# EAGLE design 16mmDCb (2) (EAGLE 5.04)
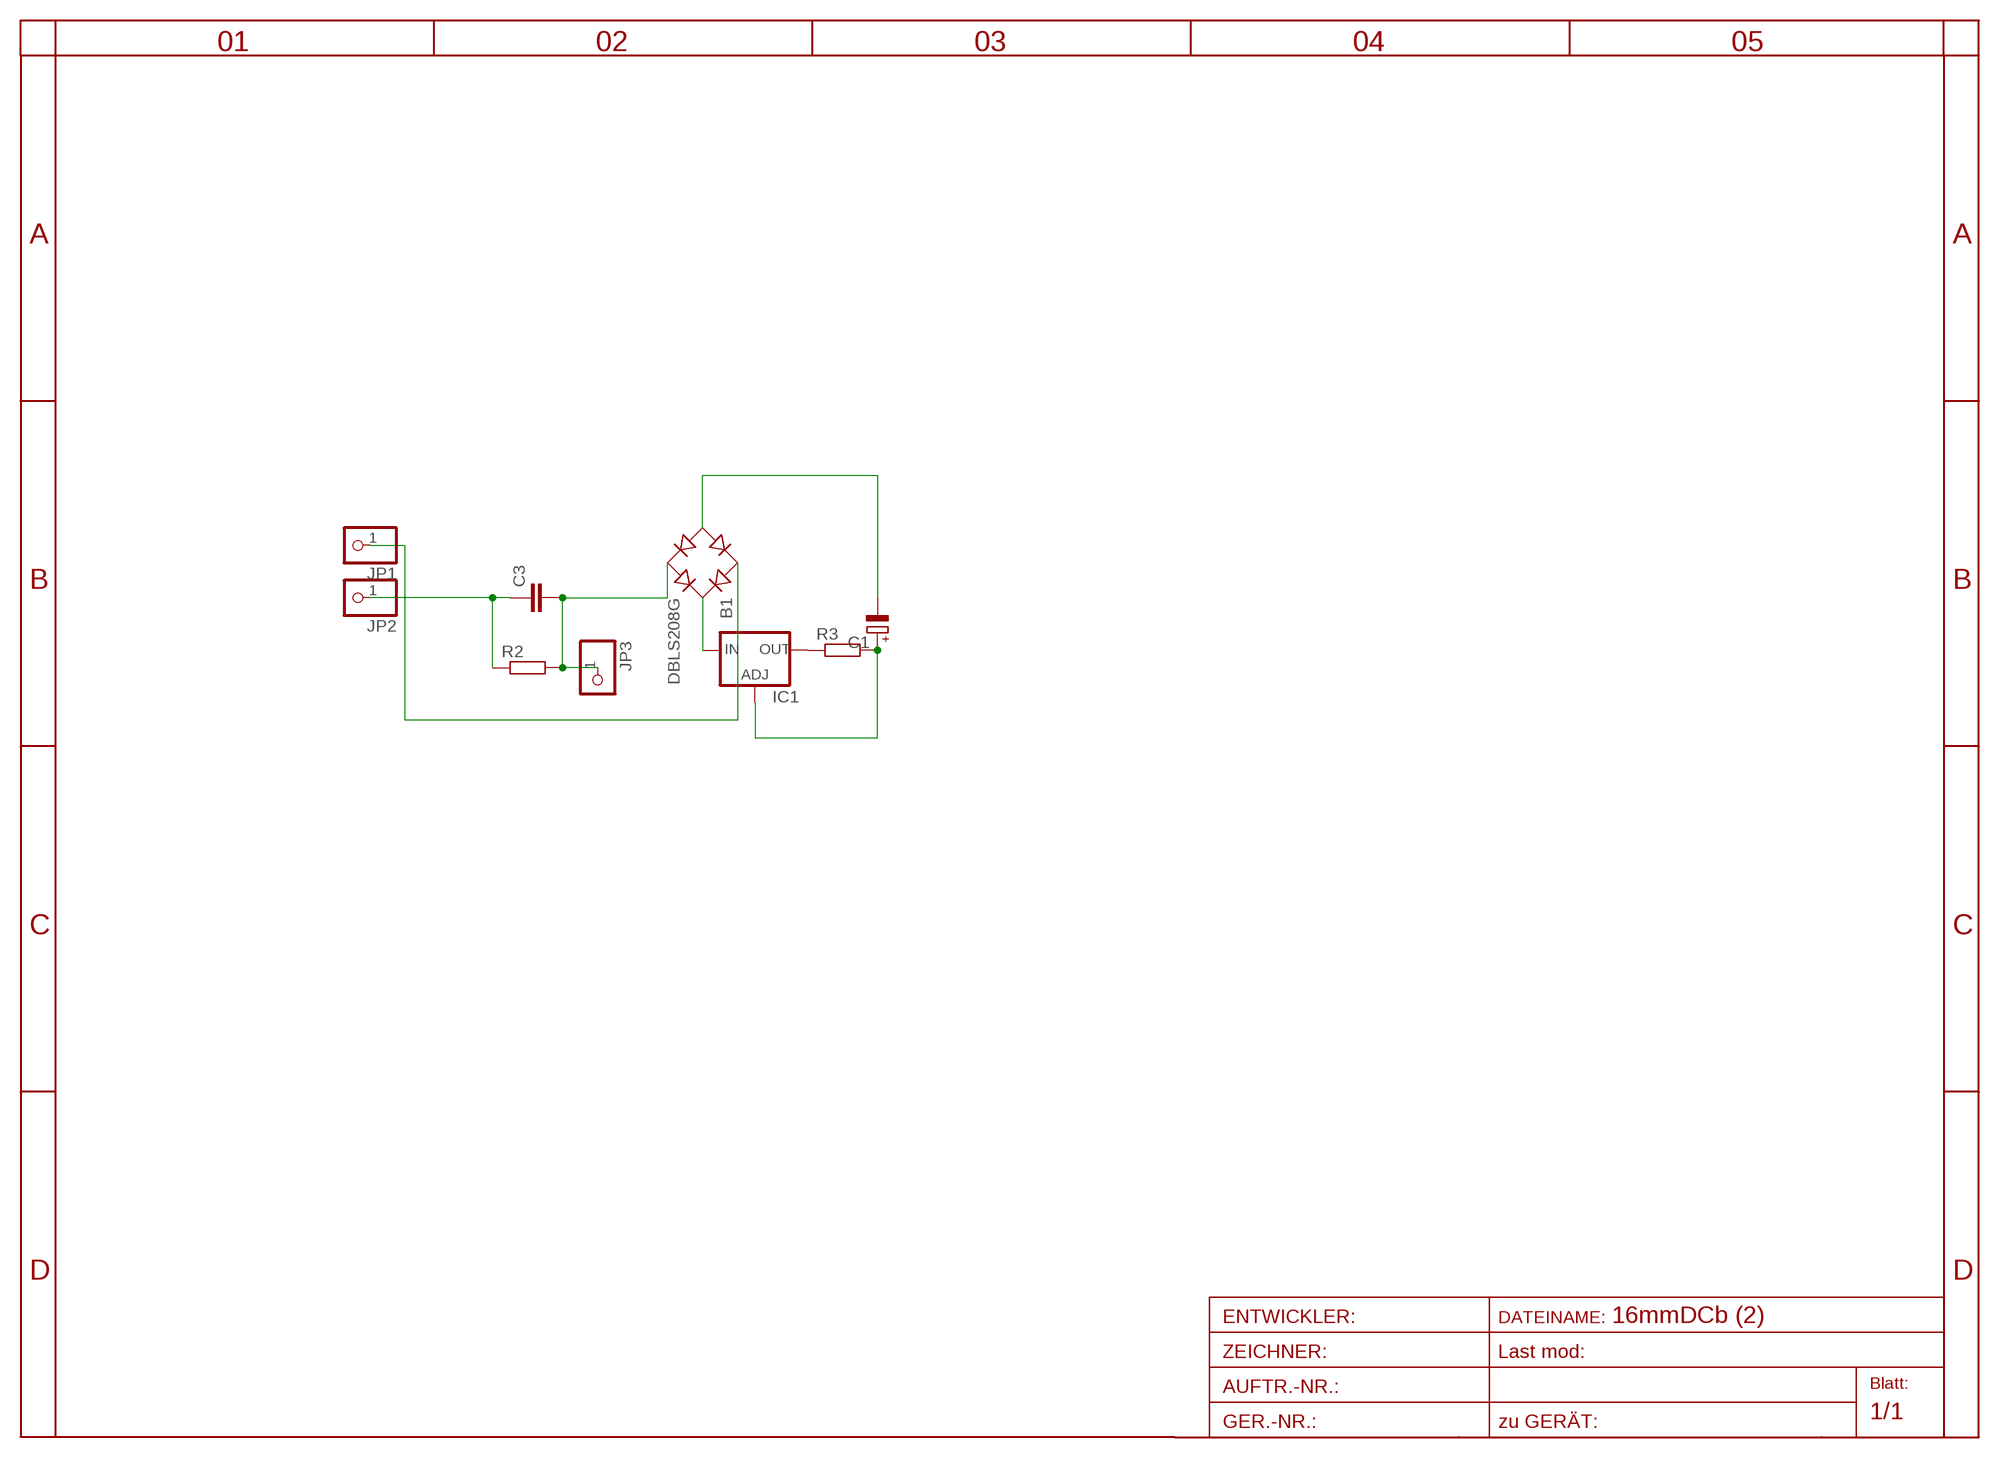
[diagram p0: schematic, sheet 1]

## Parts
B1  DBLS208G  [DBS]
C1  CPOL-EUE5-8.5  [E5-8,5]
C3  C-EU102-064X133  [C102-064X133]
IC1  LM317LZ  [317L]
JP1  PINHD-1X1  [1X01]
JP2  PINHD-1X1  [1X01]
JP3  PINHD-1X1  [1X01]
R2  R-EU_R1206  [R1206]
R3  R-EU_R1206  [R1206]

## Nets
AC: B1.AC1 JP1.1
AC+: C3.1 JP2.1 R2.1
N$1: B1.AC2 C3.2 JP3.1 R2.2
N$2: B1.+ IC1.3(IN)
N$4: C1.+ IC1.1(ADJ) R3.2
N$5: IC1.2(OUT) R3.1
N$9: B1.- C1.-

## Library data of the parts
B1 = rectifier:DB?*G: Single Phase 1.0 AMP Glass Passivated Bridge Rectifier Taiwan Semiconductor Co.,Ltd. - TSC Source: http://www.taiwansemi.com/TSCbig5/ezcatfiles/cust/img/img/db101g.pdf http://www.ts.com.tw/db/pictures/modules/PDT/PDT060207001/DBLS201G.pdf
C1 = rcl-2:CPOL-EU: POLARIZED CAPACITOR, European symbol
C3 = rcl:C-EU: CAPACITOR, European symbol
IC1 = v-reg-3:LM317L: Adjustable Voltage Regulator, 1.2V to 37V, 100mA
JP1-JP3 = pinhead:PINHD-1X1: PIN HEADER
R2 R3 = rcl:R-EU_: RESISTOR, European symbol

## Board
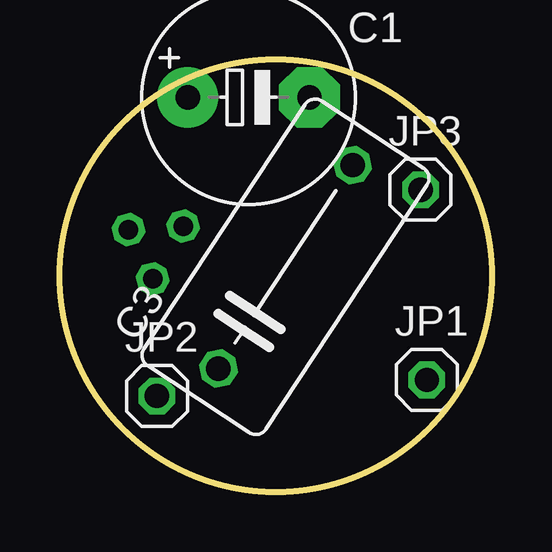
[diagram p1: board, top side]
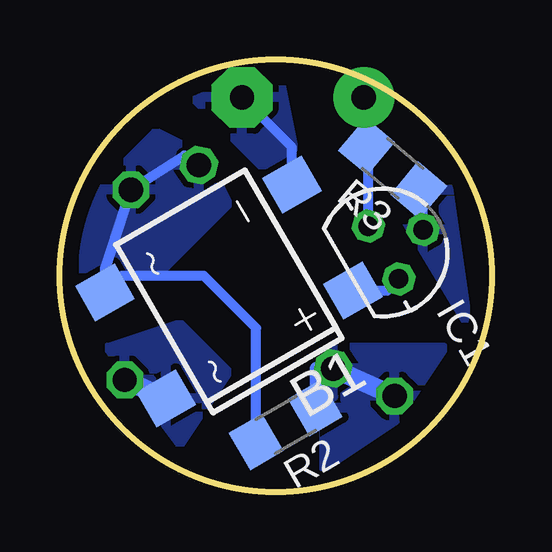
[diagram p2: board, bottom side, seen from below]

Size 18 x 18 mm. Coordinates in mm from the lower left corner, seen from the top.
Outline: circle at 9,9 radius 9
Copper layers (1*16): Top 0.035mm / dielectric 1.5mm / Bottom 0.035mm
Design rules "default *": minimum track width 10mil, minimum drill 24mil, track to track 8mil, track to pad 8mil, pad to pad 8mil, via to via 8mil, smd to smd 8mil, copper to edge 4mil, drill to drill 8mil, minimum pad ring 10mil, minimum via ring 8mil, stop-mask expansion 4mil, vias tented up to drill 0mil, thermal gap 10mil

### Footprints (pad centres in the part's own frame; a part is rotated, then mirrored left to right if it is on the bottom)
DBS = smd 1.7 x 1.9: + -2.55,-4.5; - 2.55,-4.5; AC1 -2.55,4.5; AC2 2.55,4.5
E5-8,5 = drill 1.016 pad 2.54 round: + -2.54,0 | drill 1.016 pad 2.54 octagon: - 2.54,0
C102-064X133 = drill 1.016 octagon: 1 -5.08,0; 2 5.08,0
317L = drill 0.813 octagon: 1 -1.27,0; 2 0,1.905; 3 1.27,0
1X01 = drill 1.016 octagon: 1 0,0
R1206 = smd 1.6 x 1.803: 1 -1.422,0; 2 1.422,0

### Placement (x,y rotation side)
B1  10.95,8.34 120 bottom
C1  7.87,16.44 0 top
C3  9.41,9.37 56.6 top
IC1  4.5,9.97 300 bottom
JP1  15.3,4.66 0 top
JP2  4.04,3.99 0 top
JP3  15.04,12.59 0 top
R2  8.59,2.78 210 bottom
R3  4.13,13.49 140 bottom

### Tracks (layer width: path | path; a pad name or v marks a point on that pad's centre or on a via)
AC
  Bottom 0.813: B1.AC1 JP1.1
  pour Bottom: 16,6 13,7 11,5 13,2
AC+
  Bottom 0.406: R2.1 7.35,5.19 C3.1
  Bottom 0.813: C3.1 JP2.1
  pour Bottom: 2,6 7,6 7,1 4,3
N$1
  Bottom 0.406: C3.2 12.81,14.01 JP3.1 16.12,9.27 B1.AC2 15.43,9 12,9 9.82,6.82 R2.2
  pour Bottom (isolate 0.61): 12,14 11,12 14,9 17,9 17,12 14,15
N$2
  Bottom 0.406: B1.+ 4.36,8.38 IC1.3
N$4
  Bottom 0.406: IC1.1 5.14,14.32 R3.2 5.21,16.33 C1.+
N$5
  Bottom 0.406: IC1.2 2.85,12.39 R3.1
  pour Bottom (isolate 0.61): 2,14 4,12 1,7
N$9
  Bottom 0.406: B1.- 8.33,14.36 C1.-
  pour Bottom (isolate 0.61, rank 2): 8,13 9,18 13,17 9,13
